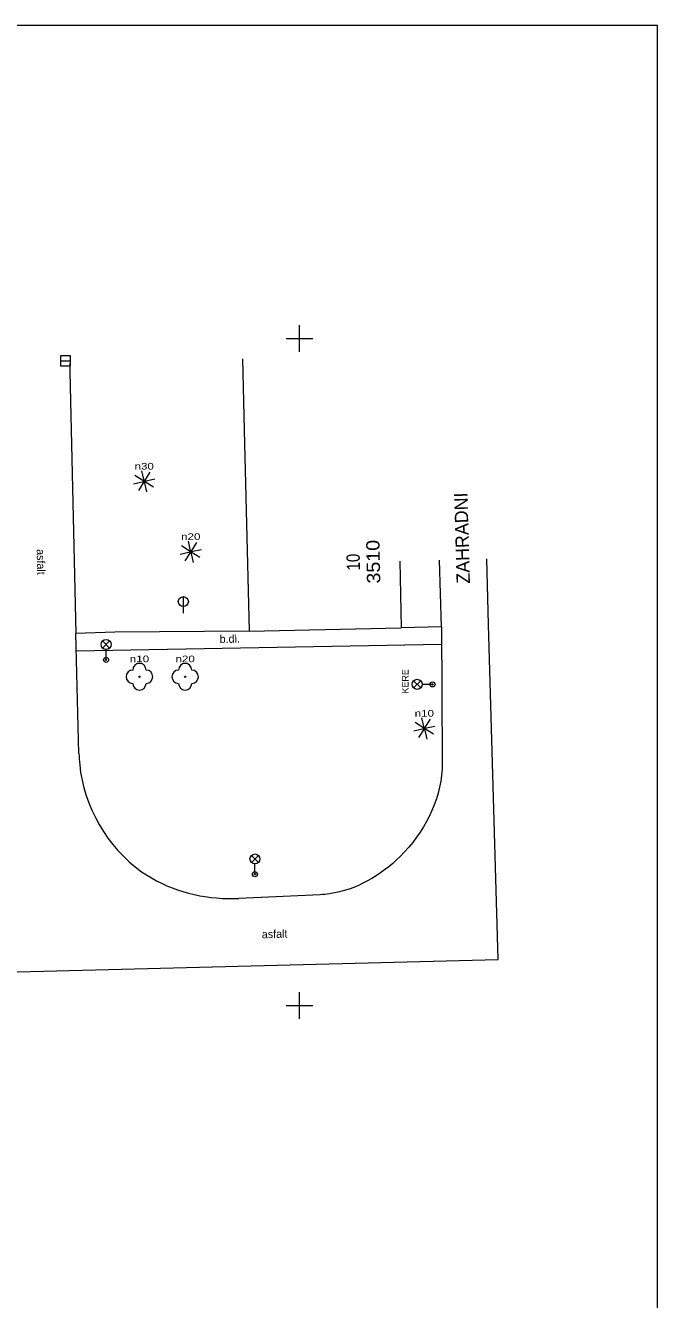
# Model space of a CAD drawing. Extents: x -670514 to -669423, y -1130798 to -1130123.
# Drawn here: x -669470.5 to -669423.2, y -1130572.1 to -1130476.5 of the extents above; entities that cross this region are included whole.
import ezdxf
from ezdxf.enums import TextEntityAlignment as Align

# ---------------------------------------------------------------- set-up
doc = ezdxf.new("R2010")
doc.units = 0
doc.header["$LTSCALE"] = 0.24
for name, color, linetype, lineweight in [('10', 7, 'Continuous', 13), ('22', 7, 'Continuous', 13), ('27', 7, 'Continuous', 13), ('33', 7, 'Continuous', 13), ('45', 7, 'Continuous', 13), ('5', 7, 'Continuous', 13), ('60', 7, 'Continuous', 13), ('61', 7, 'Continuous', 13)]:
    doc.layers.add(name, color=color, linetype=linetype, lineweight=lineweight)
for name, color, linetype in [('40', 7, 'Continuous'), ('43', 7, 'Continuous'), ('44', 7, 'Continuous')]:
    doc.layers.add(name, color=color, linetype=linetype)

msp = doc.modelspace()

# ---------------------------------------------------------------- linework, layer by layer
at = {"layer": '10'}
for p, q in [((-669467.206, -1130501.866), (-669467.192, -1130502.493)), ((-669467.192, -1130502.493), (-669466.754, -1130522.126)), ((-669435.821, -1130521.434), (-669435.958, -1130516.524)), ((-669439.355, -1130521.626), (-669439.495, -1130516.623)), ((-669466.516, -1130531.103), (-669466.754, -1130522.126)), ((-669439.355, -1130521.626), (-669442.366, -1130521.705)), ((-669439.355, -1130521.626), (-669439.297, -1130531.6)), ((-669466.72, -1130523.426), (-669439.347, -1130522.926)), ((-669448.444, -1130541.713), (-669454.542, -1130541.983))]:
    msp.add_line(p, q, dxfattribs=at)
for points in [[(-669534.98, -1130549.229), (-669533.479, -1130549.197), (-669524.922, -1130548.918), (-669521.387, -1130548.847), (-669475.034, -1130547.594), (-669435.119, -1130546.569), (-669435.821, -1130521.434)], [(-669453.771, -1130521.944), (-669463.83, -1130522.016), (-669466.754, -1130522.126)]]:
    msp.add_lwpolyline(points, dxfattribs=at)
for points in [[(-669466.516, -1130531.103), (-669466.461, -1130531.958), (-669461.819, -1130539.977), (-669455.349, -1130541.988), (-669454.542, -1130541.983)], [(-669439.297, -1130531.6), (-669439.314, -1130532.289), (-669442.445, -1130538.829), (-669447.733, -1130541.633), (-669448.444, -1130541.713)]]:
    msp.add_spline(points, degree=3, dxfattribs=at)
at = {"layer": '22'}
for p, q in [((-669462.422, -1130510.894), (-669461.668, -1130510.722)), ((-669461.662, -1130510.694), (-669462.318, -1130510.28)), ((-669461.648, -1130510.748), (-669462.062, -1130511.404)), ((-669461.636, -1130510.674), (-669461.808, -1130509.92)), ((-669461.62, -1130510.754), (-669461.448, -1130511.508)), ((-669461.194, -1130510.024), (-669461.608, -1130510.68)), ((-669460.938, -1130511.148), (-669461.594, -1130510.734)), ((-669461.588, -1130510.706), (-669460.834, -1130510.534)), ((-669458.173, -1130515.97), (-669458.829, -1130515.556)), ((-669458.147, -1130515.95), (-669458.319, -1130515.196)), ((-669457.705, -1130515.3), (-669458.119, -1130515.956)), ((-669458.933, -1130516.17), (-669458.179, -1130515.998)), ((-669458.159, -1130516.024), (-669458.573, -1130516.68)), ((-669458.131, -1130516.03), (-669457.959, -1130516.784)), ((-669457.449, -1130516.424), (-669458.105, -1130516.01)), ((-669458.099, -1130515.982), (-669457.345, -1130515.81)), ((-669440.673, -1130529.216), (-669441.329, -1130528.802)), ((-669440.647, -1130529.196), (-669440.819, -1130528.442)), ((-669440.205, -1130528.546), (-669440.619, -1130529.202)), ((-669441.433, -1130529.416), (-669440.679, -1130529.244)), ((-669440.659, -1130529.27), (-669441.073, -1130529.926)), ((-669440.631, -1130529.276), (-669440.459, -1130530.03)), ((-669439.949, -1130529.67), (-669440.605, -1130529.256)), ((-669440.599, -1130529.228), (-669439.845, -1130529.056))]:
    msp.add_line(p, q, dxfattribs=at)
for centre, radius in [((-669461.628, -1130510.714), 0.04), ((-669458.139, -1130515.99), 0.04), ((-669461.982, -1130525.356), 0.05), ((-669458.559, -1130525.359), 0.05), ((-669440.639, -1130529.236), 0.04)]:
    msp.add_circle(centre, radius, dxfattribs=at)
for centre, start, end in [((-669462.482, -1130525.356), 90, 270), ((-669461.982, -1130524.856), 0, 180), ((-669461.482, -1130525.356), 270, 90), ((-669459.059, -1130525.359), 90, 270), ((-669458.559, -1130524.859), 0, 180), ((-669458.059, -1130525.359), 270, 90), ((-669461.982, -1130525.856), 180, 0), ((-669458.559, -1130525.859), 180, 0)]:
    msp.add_arc(centre, 0.5, start, end, dxfattribs=at)
at = {"layer": '27'}
for p, q in [((-669467.902, -1130501.676), (-669467.152, -1130501.676)), ((-669458.696, -1130519.353), (-669458.696, -1130520.603))]:
    msp.add_line(p, q, dxfattribs=at)
msp.add_lwpolyline([(-669467.902, -1130502.05), (-669467.152, -1130502.05), (-669467.152, -1130501.3), (-669467.902, -1130501.3)], close=True, dxfattribs=at)
msp.add_circle((-669458.6956, -1130519.7281), 0.375, dxfattribs=at)
at = {"layer": '33'}
for p, q in [((-669464.748, -1130522.677), (-669464.218, -1130523.207)), ((-669464.748, -1130523.207), (-669464.218, -1130522.677)), ((-669464.483, -1130524.092), (-669464.483, -1130523.317)), ((-669441.445, -1130526.195), (-669440.915, -1130525.665)), ((-669440.915, -1130526.195), (-669441.445, -1130525.665)), ((-669440.03, -1130525.93), (-669440.805, -1130525.93)), ((-669453.593, -1130538.757), (-669453.063, -1130539.287)), ((-669453.593, -1130539.287), (-669453.063, -1130538.757)), ((-669453.328, -1130540.172), (-669453.328, -1130539.397))]:
    msp.add_line(p, q, dxfattribs=at)
for centre, radius in [((-669464.483, -1130522.942), 0.375), ((-669464.483, -1130524.092), 0.19), ((-669464.483, -1130524.092), 0.05), ((-669441.18, -1130525.93), 0.375), ((-669440.03, -1130525.93), 0.19), ((-669440.03, -1130525.93), 0.05), ((-669453.328, -1130539.022), 0.375), ((-669453.328, -1130540.172), 0.19), ((-669453.328, -1130540.172), 0.05)]:
    msp.add_circle(centre, radius, dxfattribs=at)
at = {"layer": '5'}
for p, q in [((-669454.268, -1130501.522), (-669454.138, -1130506.877)), ((-669442.471, -1130516.706), (-669442.366, -1130521.705))]:
    msp.add_line(p, q, dxfattribs=at)
msp.add_lwpolyline([(-669454.138, -1130506.877), (-669453.771, -1130521.944), (-669442.366, -1130521.705)], dxfattribs=at)
at = {"layer": '60'}
msp.add_lwpolyline([(-669833.172, -1130763.536), (-669423.172, -1130763.536), (-669423.172, -1130476.536), (-669833.172, -1130476.536)], close=True, dxfattribs=at)
at = {"layer": '61'}
for p, q in [((-669450, -1130501), (-669450, -1130499)), ((-669451, -1130500), (-669449, -1130500)), ((-669450, -1130551), (-669450, -1130549)), ((-669451, -1130550), (-669449, -1130550))]:
    msp.add_line(p, q, dxfattribs=at)

# ---------------------------------------------------------------- texts
at = {"layer": '22', "width": 1.3}
for s, p in [('n30', (-669461.6285, -1130509.828)), ('n20', (-669458.1395, -1130515.104)), ('n10', (-669461.9825, -1130524.27)), ('n20', (-669458.5585, -1130524.273)), ('n10', (-669440.6395, -1130528.35))]:
    msp.add_text(s, height=0.499, dxfattribs=at).set_placement(p, align=Align.CENTER)
at = {"layer": '22'}
msp.add_text('KERE', height=0.499, rotation=90, dxfattribs=at).set_placement((-669441.823, -1130525.7045), align=Align.CENTER)
at = {"layer": '40'}
for s, rotation, p in [('asfalt', 271.299, (-669469.6615, -1130516.7582)), ('b.dl.', 1.046, (-669455.212, -1130522.8218)), ('asfalt', 1.471, (-669451.8532, -1130544.9439))]:
    msp.add_text(s, height=0.6, rotation=rotation, dxfattribs=at).set_placement(p, align=Align.CENTER)
at = {"layer": '43', "width": 1.1}
msp.add_text('3510', height=1, rotation=91.203, dxfattribs=at).set_placement((-669443.9709, -1130516.727), align=Align.CENTER)
at = {"layer": '44', "width": 0.85}
msp.add_text('10', height=1, rotation=91.203, dxfattribs=at).set_placement((-669445.4701, -1130516.7585), align=Align.CENTER)
at = {"layer": '45'}
msp.add_text('ZAHRADNI', height=1, rotation=91.6, dxfattribs=at).set_placement((-669437.317, -1130514.9545), align=Align.CENTER)

doc.saveas('drawing.dxf')
